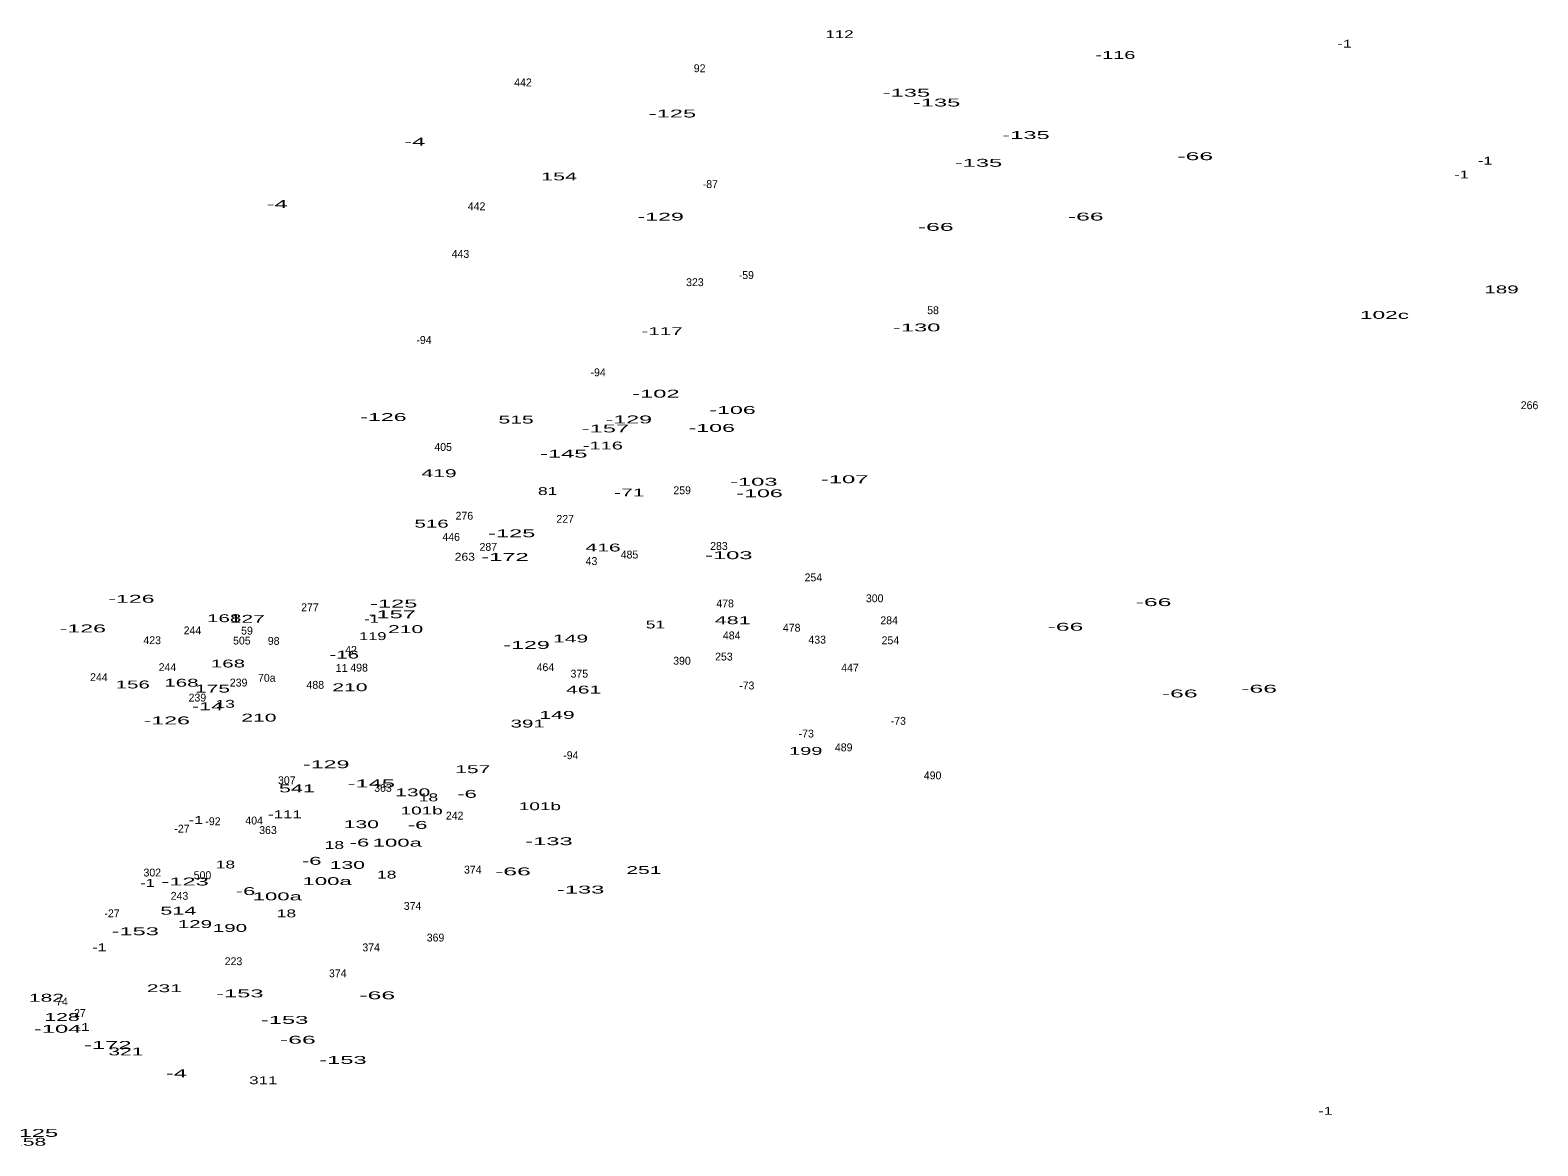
# Model space of a CAD drawing. Extents: x -662280 to -658689, y -991723 to -987042.
# Drawn here: x -661656 to -660890, y -990002 to -989435 of the extents above; entities that cross this region are included whole.
import ezdxf
from ezdxf.enums import TextEntityAlignment as Align

# ---------------------------------------------------------------- set-up
doc = ezdxf.new("R2010")
doc.units = 0
doc.header["$LTSCALE"] = 1.6
doc.layers.add('24', color=7, linetype='Continuous')

msp = doc.modelspace()

# ---------------------------------------------------------------- texts
at = {"layer": '24'}
for s, width, p in [('112', 1.6, (-661244.864, -989439.42)), ('-1', 1.55, (-660988.201, -989444.25)), ('-116', 1.9, (-661104.681, -989449.98)), ('-135', 2.25, (-661210.881, -989469.15)), ('-135', 2.25, (-661195.531, -989474.13)), ('-125', 2.25, (-661329.761, -989479.72)), ('-135', 2.25, (-661150.111, -989490.66)), ('-4', 2.25, (-661460.76, -989494.05)), ('-135', 2.25, (-661174.251, -989504.75)), ('-66', 2.35, (-661064.103, -989501.39)), ('-1', 1.55, (-660916.791, -989503.67)), ('154', 2.05, (-661387.383, -989511.67)), ('-1', 1.55, (-660928.821, -989510.66)), ('-4', 2.25, (-661530.62, -989525.7)), ('-129', 2.2, (-661335.765, -989532.13)), ('-66', 2.35, (-661195.973, -989537.3)), ('-66', 2.35, (-661119.753, -989532.06)), ('189', 1.95, (-660908.473, -989569.06)), ('102c', 2.15, (-660967.943, -989582.01)), ('-117', 1.95, (-661335.041, -989590.25)), ('-130', 2.25, (-661205.667, -989588.38)), ('-102', 2.25, (-661338.177, -989622.03)), ('-126', 2.2, (-661476.625, -989633.9)), ('515', 2, (-661409.217, -989635.19)), ('-129', 2.2, (-661351.945, -989635.11)), ('-106', 2.2, (-661299.231, -989630.33)), ('-157', 2.25, (-661363.815, -989639.7)), ('-106', 2.2, (-661309.791, -989639.42)), ('-145', 2.25, (-661385.016, -989652.52)), ('-116', 1.9, (-661365.121, -989648.37)), ('419', 2, (-661448.368, -989662.42)), ('-103', 2.25, (-661288.437, -989666.77)), ('-107', 2.25, (-661242.261, -989665.49)), ('81', 1.65, (-661393.197, -989671.49)), ('-71', 2, (-661351.695, -989672.23)), ('-106', 2.2, (-661285.501, -989672.6)), ('516', 1.95, (-661452.163, -989688.06)), ('-125', 2.25, (-661411.441, -989692.96)), ('263', 1.15, (-661435.29, -989704.87)), ('-172', 2.25, (-661414.855, -989704.96)), ('416', 2, (-661365.018, -989700.18)), ('-103', 2.25, (-661301.137, -989704.08)), ('-126', 2.2, (-661604.705, -989726.23)), ('-125', 2.25, (-661471.401, -989728.65)), ('-66', 2.35, (-661085.283, -989727.93)), ('168', 1.95, (-661557.553, -989736.08)), ('127', 2, (-661545.813, -989736.41)), ('-1', 1.55, (-661482.721, -989736.41)), ('-157', 2.25, (-661472.145, -989734.09)), ('-126', 2.2, (-661629.405, -989741.28)), ('210', 2, (-661465.354, -989741.64)), ('51', 1.65, (-661338.417, -989739.29)), ('481', 2.05, (-661299.153, -989737.13)), ('-66', 2.35, (-661130.053, -989740.44)), ('119', 1.55, (-661482.039, -989745.2)), ('-129', 2.2, (-661403.885, -989749.68)), ('149', 2, (-661381.528, -989746.41)), ('168', 1.95, (-661555.643, -989759.11)), ('-16', 1.95, (-661496.565, -989754.59)), ('11', 1.05, (-661497.894, -989761.41)), ('156', 1.95, (-661604.023, -989769.76)), ('168', 1.95, (-661579.283, -989768.87)), ('175', 2, (-661563.493, -989771.84)), ('210', 2, (-661493.654, -989771.16)), ('461', 2, (-661374.888, -989772.35)), ('-66', 2.35, (-661071.973, -989774.33)), ('-66', 2.35, (-661031.653, -989771.91)), ('-14', 2.05, (-661566.036, -989780.86)), ('13', 1.65, (-661557.027, -989779.59)), ('-126', 2.2, (-661586.735, -989788.02)), ('210', 2, (-661539.904, -989786.61)), ('391', 1.95, (-661403.333, -989789.61)), ('149', 2, (-661388.418, -989785.21)), ('199', 1.9, (-661262.047, -989803.49)), ('-129', 2.2, (-661505.695, -989810.29)), ('157', 2, (-661431.233, -989812.78)), ('-145', 2.25, (-661482.816, -989820.02)), ('541', 2.05, (-661520.593, -989822.55)), ('130', 2, (-661461.744, -989824.55)), ('18', 1.65, (-661453.737, -989827.13)), ('-6', 2.1, (-661434.159, -989825.32)), ('-111', 1.6, (-661526.723, -989835.73)), ('101b', 1.8, (-661457.205, -989833.78)), ('101b', 1.8, (-661397.125, -989831.6)), ('-1', 1.55, (-661571.881, -989838.58)), ('130', 2, (-661487.864, -989840.73)), ('-6', 2.1, (-661459.259, -989841.11)), ('18', 1.65, (-661501.547, -989851.28)), ('-6', 2.1, (-661488.809, -989850.03)), ('100a', 2.1, (-661469.595, -989850.12)), ('-133', 2.25, (-661392.521, -989849.37)), ('-6', 2.1, (-661513.099, -989859.34)), ('18', 1.65, (-661556.937, -989861.22)), ('130', 2, (-661494.974, -989861.42)), ('18', 1.65, (-661474.937, -989866.33)), ('-66', 2.35, (-661410.823, -989864.71)), ('251', 2, (-661344.277, -989864.04)), ('-1', 1.55, (-661596.521, -989870.56)), ('-123', 2.25, (-661577.431, -989869.86)), ('-6', 2.1, (-661546.699, -989874.73)), ('100a', 2.1, (-661505.245, -989869.65)), ('-133', 2.25, (-661376.421, -989873.94)), ('100a', 2.1, (-661530.575, -989877.39)), ('514', 2.05, (-661580.853, -989884.69)), ('18', 1.65, (-661525.917, -989886.04)), ('-153', 2.25, (-661602.761, -989895.12)), ('129', 1.95, (-661572.433, -989891.48)), ('190', 1.95, (-661554.629, -989893.44)), ('-1', 1.55, (-661620.971, -989903.24)), ('231', 2, (-661587.957, -989924.06)), ('-153', 2.25, (-661549.611, -989926.69)), ('-66', 2.35, (-661479.783, -989927.66)), ('182', 2, (-661647.897, -989928.9)), ('128', 2, (-661639.967, -989938.68)), ('-153', 2.25, (-661526.851, -989940.15)), ('-104', 2.25, (-661642.192, -989944.69)), ('-1', 1.55, (-661629.511, -989943.79)), ('-66', 2.35, (-661520.113, -989950.25)), ('-172', 2.25, (-661616.705, -989952.89)), ('321', 2, (-661607.507, -989956.18)), ('-153', 2.25, (-661497.201, -989960.5)), ('-4', 2.25, (-661581.86, -989967.31)), ('311', 1.6, (-661537.684, -989970.81)), ('-1', 1.55, (-660997.951, -989986.36)), ('-125', 2.25, (-661653.981, -989997.56)), ('158', 2, (-661656.927, -990002.07))]:
    msp.add_text(s, height=4, dxfattribs=dict(at, width=width)).set_placement(p, align=Align.CENTER)
for s, p in [('92', (-661315.953, -989456.71)), ('442', (-661405.706, -989463.91)), ('-87', (-661310.511, -989515.57)), ('442', (-661429.296, -989526.81)), ('443', (-661437.496, -989551.03)), ('323', (-661318.367, -989565.39)), ('-59', (-661292.23, -989561.79)), ('58', (-661197.347, -989579.63)), ('-94', (-661456.025, -989594.75)), ('-94', (-661367.525, -989611.19)), ('266', (-660894.238, -989627.88)), ('405', (-661446.295, -989649.1)), ('259', (-661324.853, -989671.1)), ('276', (-661435.518, -989684.04)), ('227', (-661384.253, -989685.63)), ('446', (-661442.211, -989694.82)), ('287', (-661423.333, -989699.86)), ('485', (-661351.601, -989703.75)), ('283', (-661306.147, -989699.4)), ('43', (-661370.921, -989707.06)), ('254', (-661258.161, -989715.35)), ('478', (-661303.007, -989728.59)), ('300', (-661227.005, -989725.98)), ('277', (-661513.989, -989730.55)), ('244', (-661573.686, -989742.29)), ('59', (-661545.983, -989742.41)), ('478', (-661269.177, -989740.93)), ('284', (-661219.661, -989737.17)), ('423', (-661594.141, -989747.27)), ('505', (-661548.581, -989747.46)), ('98', (-661532.403, -989747.6)), ('42', (-661493.081, -989752.2)), ('484', (-661299.666, -989744.84)), ('433', (-661256.211, -989746.98)), ('254', (-661219.011, -989747.31)), ('390', (-661324.937, -989757.69)), ('253', (-661303.617, -989755.57)), ('244', (-661621.226, -989766.04)), ('244', (-661586.386, -989760.96)), ('70a', (-661535.911, -989766.37)), ('498', (-661488.987, -989761.18)), ('498', (-661488.987, -989761.18)), ('464', (-661394.341, -989760.99)), ('375', (-661377.103, -989764.27)), ('447', (-661239.531, -989761.22)), ('239', (-661550.233, -989768.79)), ('488', (-661511.271, -989769.94)), ('-73', (-661292.011, -989770.27)), ('239', (-661571.183, -989776.41)), ('-73', (-661214.991, -989788.23)), ('-73', (-661261.771, -989794.68)), ('-94', (-661381.415, -989805.67)), ('489', (-661242.747, -989801.7)), ('307', (-661525.747, -989818.43)), ('490', (-661197.571, -989815.94)), ('363', (-661476.873, -989822.28)), ('242', (-661440.451, -989836.37)), ('-27', (-661579.011, -989843.01)), ('-92', (-661563.26, -989839.25)), ('404', (-661542.34, -989838.88)), ('363', (-661535.303, -989843.74)), ('302', (-661594.081, -989865.29)), ('500', (-661568.595, -989866.63)), ('374', (-661431.237, -989863.79)), ('243', (-661580.271, -989877.13)), ('374', (-661461.827, -989882.28)), ('-27', (-661614.551, -989886.01)), ('374', (-661482.867, -989903.31)), ('369', (-661450.158, -989898.32)), ('223', (-661552.827, -989910.34)), ('374', (-661499.867, -989916.49)), ('74', (-661639.997, -989930.8)), ('-27', (-661631.761, -989936.64))]:
    msp.add_text(s, height=4, dxfattribs=at).set_placement(p, align=Align.CENTER)

doc.saveas('drawing.dxf')
